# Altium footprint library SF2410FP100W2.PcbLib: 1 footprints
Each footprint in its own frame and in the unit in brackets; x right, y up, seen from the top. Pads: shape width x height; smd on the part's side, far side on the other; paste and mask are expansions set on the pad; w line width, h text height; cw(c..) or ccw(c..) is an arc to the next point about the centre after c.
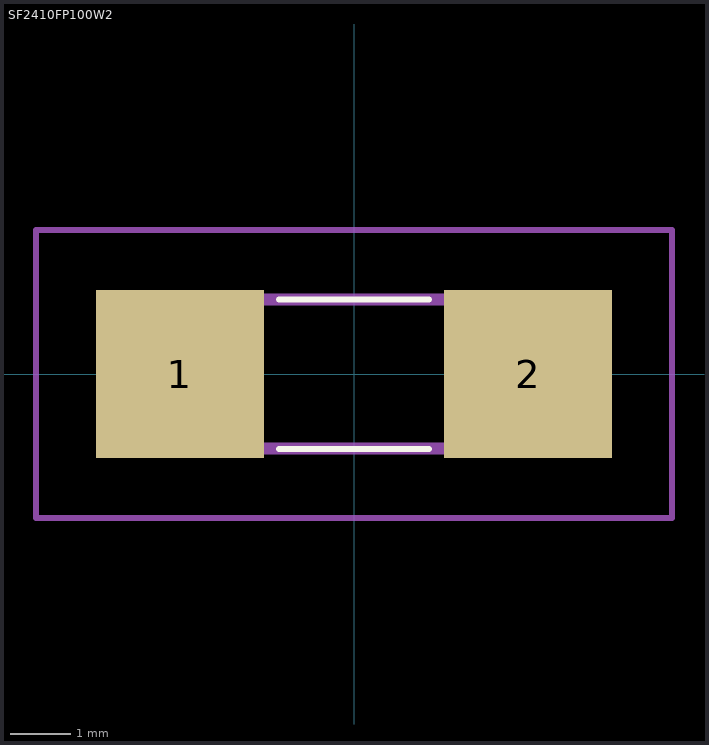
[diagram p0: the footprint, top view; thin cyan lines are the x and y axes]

## SF2410FP100W2 [mm]
pads (2):
  rect 2.8x2.8 smd: 1(-2.9,0) 2(2.9,0)
Top Overlay:
  lines w0.1: -1.25,-1.25 1.25,-1.25 ; -1.25,1.245 1.25,1.245 ; 1.25,-1.25 1.25,-1.25
Mechanical 15:
  lines w0.2: -3.05,-1.245 3.05,-1.245 3.05,1.245 -3.05,1.245 -3.05,-1.245
Mechanical 20:
  lines w0.1: -5.3,-2.4 5.3,-2.4 5.3,2.4 -5.3,2.4 -5.3,-2.4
